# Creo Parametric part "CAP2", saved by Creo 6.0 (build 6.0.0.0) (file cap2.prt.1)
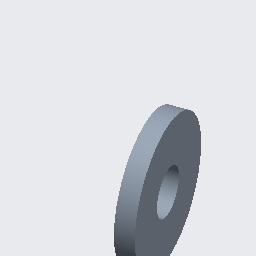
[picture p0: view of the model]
Units: millimeter Newton Second (mmNs); MM, TONNE, SECS

Created from: MMNS_PART_SOLID.PRT

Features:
  1. datum plane "RIGHT"
  2. datum plane "TOP"
  3. datum plane "FRONT"
  4. coordinate system
  5. sketch "Sketch 1"
  6. extrusion "Extrude 1"

Surfaces: 2 plane, 2 cylinder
